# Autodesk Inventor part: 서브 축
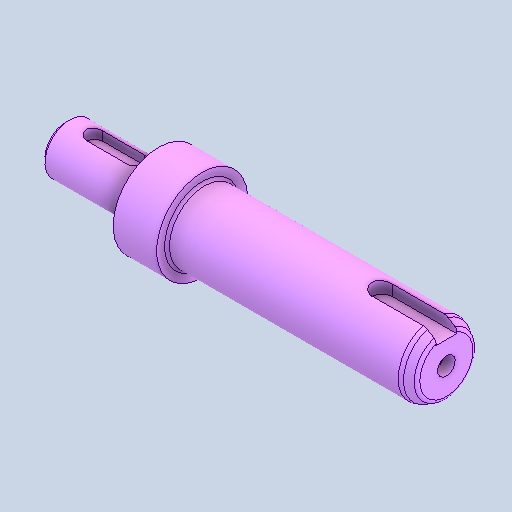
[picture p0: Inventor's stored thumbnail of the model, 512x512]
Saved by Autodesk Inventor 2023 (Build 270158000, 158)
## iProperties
Created: 2025-04
Part Number: 서브 축
Material: 강철, 탄소
Document SubType Name: Modeling
Designer: User
Density: 7.85 g/cm^3
Appearance: 기본값
Author: jhkim
Sending System: Autodesk Inventor 2026
Preprocessor: ST-DEVELOPER v20.1
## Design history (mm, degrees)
feature "솔리드1"
node "솔리드2"
